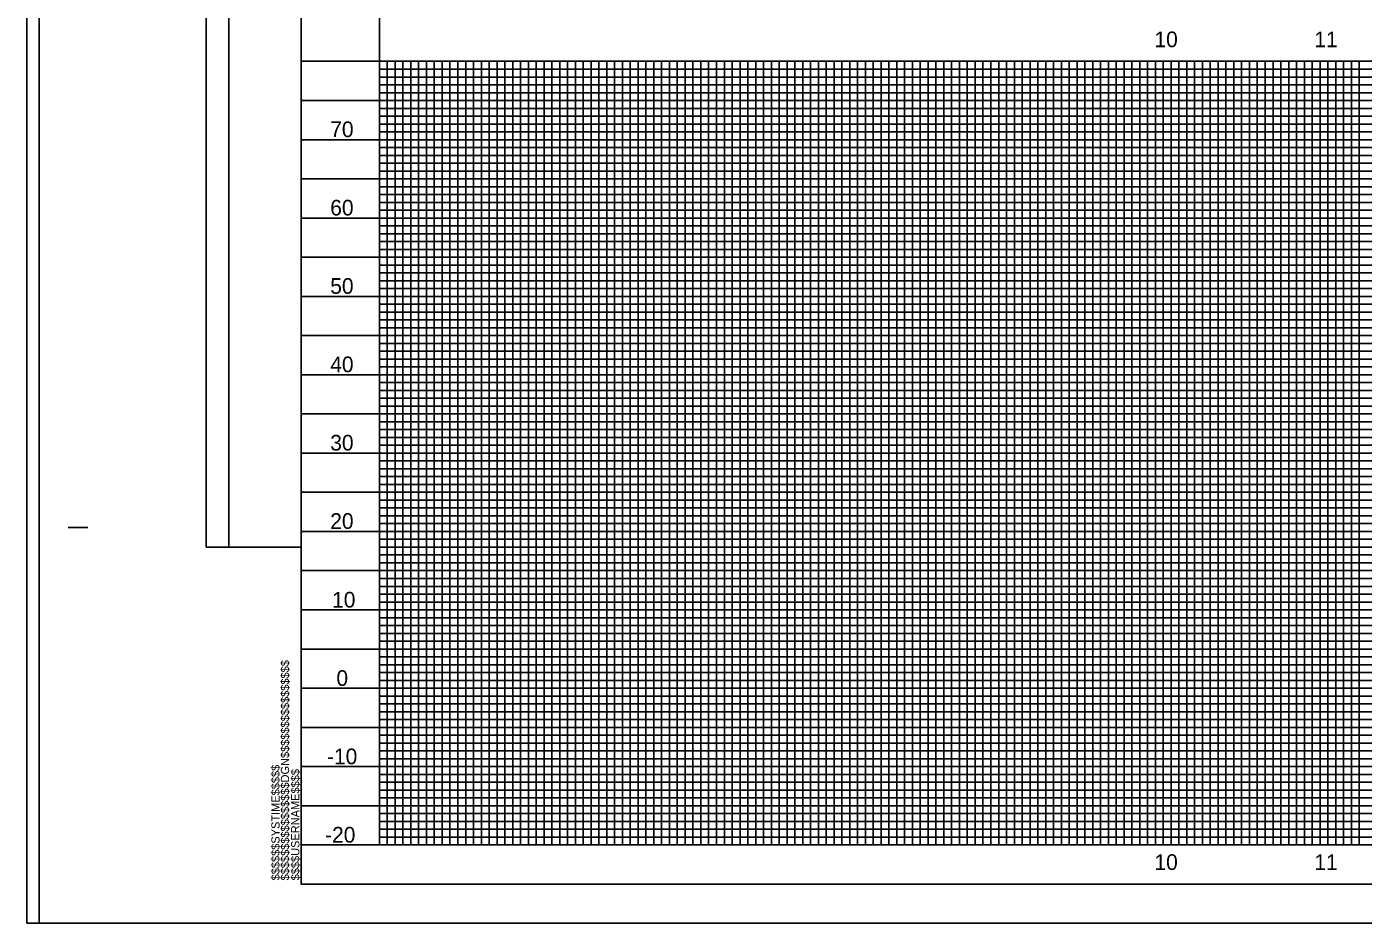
# Model space of a CAD drawing. Extents: x 1637092 to 1638792, y 884647 to 885778.
# Drawn here: x 1637092 to 1637944, y 884647 to 885219 of the extents above; entities that cross this region are included whole.
import ezdxf

# ---------------------------------------------------------------- set-up
doc = ezdxf.new("R2010")
doc.units = 0
for name, color, linetype in [('Exist Vertical Profile Horizontal Axis Label Major', 7, 'Continuous'), ('Exist Vertical Profile Vertical Axis Label', 7, 'Continuous'), ('Scratch_Level_3', 7, 'Continuous'), ('Sheet Block Revision CELL', 7, 'Continuous'), ('Sheet Block System Information CELL', 7, 'Continuous'), ('Sheet Cutting Line CELL', 7, 'Continuous'), ('Sheet DOT Grid CELL', 7, 'Continuous'), ('Sheet Layout Profile Border Port 2', 7, 'Continuous'), ('Sheet Plan And Profile CELL', 7, 'Continuous'), ('Sheet Profile CELL', 7, 'Continuous'), ('Sheet Profile Grid Major CELL', 7, 'Continuous'), ('Sheet Profile Grid Middle CELL', 7, 'Continuous'), ('Sheet Profile Grid Minor CELL', 7, 'Continuous'), ('Stewart Plot Border Xerox6279 and LJ5000', 7, 'Continuous')]:
    doc.layers.add(name, color=color, linetype=linetype)

msp = doc.modelspace()

# ---------------------------------------------------------------- linework, layer by layer
at = {"layer": 'Scratch_Level_3'}
msp.add_lwpolyline([(1637316.66, 885722.14), (1637316.66, 884697.14), (1638716.66, 884697.14), (1638716.66, 885777.71)], close=True, dxfattribs=at)
at = {"layer": 'Sheet Block Revision CELL'}
msp.add_line((1637220.66, 884887.14), (1637220.66, 885677.79), dxfattribs=at)
msp.add_lwpolyline([(1637206.11, 884887.14), (1637206.11, 885677.79), (1637266.66, 885677.79), (1637266.66, 884887.14)], close=True, dxfattribs=at)
at = {"layer": 'Sheet Block System Information CELL'}
msp.add_line((1637266.66, 884672.14), (1637266.66, 884672.14), dxfattribs=at)
at = {"layer": 'Sheet Cutting Line CELL'}
for p, q in [((1637099.66, 885747.14), (1637099.66, 884647.14)), ((1637099.66, 884647.14), (1638783.66, 884647.14))]:
    msp.add_line(p, q, dxfattribs=at)
at = {"layer": 'Sheet DOT Grid CELL'}
for p, q in [((1637266.66, 885197.14), (1638766.54, 885197.14)), ((1637316.66, 885197.14), (1637316.66, 884697.14)), ((1637366.66, 885197.14), (1637366.66, 884697.14)), ((1637416.66, 885197.14), (1637416.66, 884697.14)), ((1637466.66, 885197.14), (1637466.66, 884697.14)), ((1637516.66, 885197.14), (1637516.66, 884697.14)), ((1637566.66, 885197.14), (1637566.66, 884697.14)), ((1637616.66, 885197.14), (1637616.66, 884697.14)), ((1637666.66, 885197.14), (1637666.66, 884697.14)), ((1637716.66, 885197.14), (1637716.66, 884697.14)), ((1637766.66, 885197.14), (1637766.66, 884697.14)), ((1637816.66, 885197.14), (1637816.66, 884697.14)), ((1637866.66, 885197.14), (1637866.66, 884697.14)), ((1637916.66, 885197.14), (1637916.66, 884697.14)), ((1637266.66, 885147.14), (1638766.54, 885147.14)), ((1637266.66, 885097.14), (1638766.54, 885097.14)), ((1637266.66, 885047.14), (1638766.54, 885047.14)), ((1637266.66, 884997.14), (1638766.54, 884997.14)), ((1637266.66, 884947.14), (1638766.54, 884947.14)), ((1637266.66, 884897.14), (1638766.54, 884897.14)), ((1637266.66, 884847.14), (1638766.54, 884847.14)), ((1637266.66, 884797.14), (1638766.54, 884797.14)), ((1637266.66, 884747.14), (1638766.54, 884747.14))]:
    msp.add_line(p, q, dxfattribs=at)
at = {"layer": 'Sheet Layout Profile Border Port 2'}
msp.add_lwpolyline([(1637316.66, 885197.14), (1638716.66, 885197.14), (1638716.66, 884697.14), (1637316.66, 884697.14)], close=True, dxfattribs=at)
at = {"layer": 'Sheet Plan And Profile CELL'}
for p, q in [((1637118.16, 884899.64), (1637130.66, 884899.64)), ((1637266.66, 884672.14), (1637266.66, 884672.14)), ((1637266.66, 884672.14), (1637266.66, 884672.14)), ((1637266.66, 884672.14), (1637266.66, 884672.14)), ((1637266.66, 884672.14), (1637266.66, 884672.14)), ((1637266.66, 884672.14), (1637266.66, 884672.14))]:
    msp.add_line(p, q, dxfattribs=at)
msp.add_lwpolyline([(1638766.66, 885722.14), (1637266.66, 885722.14), (1637266.66, 884672.14), (1638766.66, 884672.14)], close=True, dxfattribs=at)
at = {"layer": 'Sheet Profile CELL'}
for p, q in [((1637266.66, 885197.14), (1638766.66, 885197.14)), ((1637118.16, 884899.64), (1637130.66, 884899.64)), ((1638766.66, 884697.14), (1637266.66, 884697.14)), ((1638766.66, 884697.14), (1637266.66, 884697.14)), ((1637266.66, 884672.14), (1638766.66, 884672.14)), ((1637266.66, 884672.14), (1637266.66, 884672.14)), ((1637266.66, 884672.14), (1637266.66, 884672.14)), ((1637266.66, 884672.14), (1637266.66, 884672.14)), ((1637266.66, 884672.14), (1637266.66, 884672.14)), ((1637266.66, 884672.14), (1637266.66, 884672.14)), ((1637266.66, 884672.14), (1637266.66, 884672.14)), ((1637266.66, 884672.14), (1637266.66, 884672.14))]:
    msp.add_line(p, q, dxfattribs=at)
msp.add_lwpolyline([(1638766.66, 885722.14), (1637266.66, 885722.14), (1637266.66, 884672.14), (1638766.66, 884672.14)], close=True, dxfattribs=at)
msp.add_lwpolyline([(1637304.16, 884672.14), (1637304.16, 884672.14)], dxfattribs=at)
at = {"layer": 'Sheet Profile Grid Major CELL'}
msp.add_line((1637266.66, 884697.14), (1637266.66, 884697.14), dxfattribs=at)
for points in [[(1637316.66, 885197.14), (1637316.66, 884697.14), (1637366.66, 884697.14), (1637366.66, 885197.14), (1637416.66, 885197.14), (1637416.66, 884697.14), (1637466.66, 884697.14), (1637466.66, 885197.14), (1637516.66, 885197.14), (1637516.66, 884697.14), (1637566.66, 884697.14), (1637566.66, 885197.14), (1637616.66, 885197.14), (1637616.66, 884697.14), (1637666.66, 884697.14), (1637666.66, 885197.14), (1637716.66, 885197.14), (1637716.66, 884697.14), (1637766.66, 884697.14), (1637766.66, 885197.14), (1637816.66, 885197.14), (1637816.66, 884697.14), (1637866.66, 884697.14), (1637866.66, 885197.14), (1637916.66, 885197.14), (1637916.66, 884697.14), (1637966.66, 884697.14)], [(1638766.66, 885147.14), (1637266.66, 885147.14)], [(1638766.66, 885097.14), (1637266.66, 885097.14), (1637266.66, 885047.14), (1638766.66, 885047.14)], [(1638766.66, 884997.14), (1637266.66, 884997.14), (1637266.66, 884947.14), (1638766.66, 884947.14)], [(1638766.66, 884897.14), (1637266.66, 884897.14), (1637266.66, 884847.14), (1638766.66, 884847.14)], [(1638766.66, 884797.14), (1637266.66, 884797.14), (1637266.66, 884797.14), (1637266.66, 884747.14), (1638766.66, 884747.14)], [(1638766.66, 884697.14), (1637266.66, 884697.14)]]:
    msp.add_lwpolyline(points, dxfattribs=at)
at = {"layer": 'Sheet Profile Grid Middle CELL'}
for points in [[(1637291.66, 885197.14), (1637341.66, 885197.14), (1637341.66, 884697.14), (1637391.66, 884697.14), (1637391.66, 885197.14), (1637441.66, 885197.14), (1637441.66, 884697.14), (1637491.66, 884697.14), (1637491.66, 885197.14), (1637541.66, 885197.14), (1637541.66, 884697.14), (1637591.66, 884697.14), (1637591.66, 885197.14), (1637641.66, 885197.14), (1637641.66, 884697.14), (1637691.66, 884697.14), (1637691.66, 885197.14), (1637741.66, 885197.14), (1637741.66, 884697.14), (1637791.66, 884697.14), (1637791.66, 885197.14), (1637841.66, 885197.14), (1637841.66, 884697.14), (1637891.66, 884697.14), (1637891.66, 884697.14), (1637891.66, 885197.14), (1637941.66, 885197.14), (1637941.66, 884697.14), (1637991.66, 884697.14)], [(1637266.66, 885172.14), (1638766.66, 885172.14)], [(1638766.66, 885122.14), (1637266.66, 885122.14), (1637266.66, 885072.14), (1638766.66, 885072.14)], [(1638766.66, 885022.14), (1637266.66, 885022.14), (1637266.66, 884972.14), (1638766.66, 884972.14)], [(1638766.66, 884922.14), (1637266.66, 884922.14), (1637266.66, 884872.14), (1638766.66, 884872.14)], [(1638766.66, 884822.14), (1637266.66, 884822.14), (1637266.66, 884772.14), (1638766.66, 884772.14)], [(1638766.66, 884722.14), (1637266.66, 884722.14)]]:
    msp.add_lwpolyline(points, dxfattribs=at)
at = {"layer": 'Sheet Profile Grid Minor CELL'}
for p, q in [((1637316.66, 885192.14), (1638716.66, 885192.14)), ((1638716.66, 885187.14), (1637316.66, 885187.14)), ((1637316.66, 885182.14), (1638716.66, 885182.14)), ((1638716.66, 885177.14), (1637316.66, 885177.14)), ((1637316.66, 885167.14), (1638716.66, 885167.14)), ((1638716.66, 885162.14), (1637316.66, 885162.14)), ((1637316.66, 885157.14), (1638716.66, 885157.14)), ((1638716.66, 885152.14), (1637316.66, 885152.14)), ((1637316.66, 885142.14), (1638716.66, 885142.14)), ((1638716.66, 885137.14), (1637316.66, 885137.14)), ((1637316.66, 885132.14), (1638716.66, 885132.14)), ((1638716.66, 885127.14), (1637316.66, 885127.14)), ((1637316.66, 885117.14), (1638716.66, 885117.14)), ((1638716.66, 885112.14), (1637316.66, 885112.14)), ((1637316.66, 885107.14), (1638716.66, 885107.14)), ((1638716.66, 885102.14), (1637316.66, 885102.14)), ((1637316.66, 885092.14), (1638716.66, 885092.14)), ((1638716.66, 885087.14), (1637316.66, 885087.14)), ((1637316.66, 885082.14), (1638716.66, 885082.14)), ((1638716.66, 885077.14), (1637316.66, 885077.14)), ((1637316.66, 885067.14), (1638716.66, 885067.14)), ((1638716.66, 885062.14), (1637316.66, 885062.14)), ((1637316.66, 885057.14), (1638716.66, 885057.14)), ((1638716.66, 885052.14), (1637316.66, 885052.14)), ((1637316.66, 885042.14), (1638716.66, 885042.14)), ((1638716.66, 885037.14), (1637316.66, 885037.14)), ((1637316.66, 885032.14), (1638716.66, 885032.14)), ((1638716.66, 885027.14), (1637316.66, 885027.14)), ((1637316.66, 885017.14), (1638716.66, 885017.14)), ((1638716.66, 885012.14), (1637316.66, 885012.14)), ((1637316.66, 885007.14), (1638716.66, 885007.14)), ((1638716.66, 885002.14), (1637316.66, 885002.29)), ((1637316.66, 884992.14), (1638716.66, 884992.14)), ((1638716.66, 884987.14), (1637316.66, 884987.14)), ((1637316.66, 884982.14), (1638716.66, 884982.14)), ((1638716.66, 884977.14), (1637316.66, 884977.14)), ((1637316.66, 884967.14), (1638716.66, 884967.14)), ((1638716.66, 884962.14), (1637316.66, 884962.14)), ((1637316.66, 884957.14), (1638716.66, 884957.14)), ((1638716.66, 884952.14), (1637316.66, 884952.14)), ((1637316.66, 884942.14), (1638716.66, 884942.14)), ((1638716.66, 884937.14), (1637316.66, 884937.14)), ((1637316.66, 884932.14), (1638716.66, 884932.14)), ((1638716.66, 884927.14), (1637316.66, 884927.14)), ((1637316.66, 884917.14), (1638716.66, 884917.14)), ((1638716.66, 884912.14), (1637316.66, 884912.14)), ((1637316.66, 884907.14), (1638716.66, 884907.14)), ((1638716.66, 884902.14), (1637316.66, 884902.14)), ((1637316.66, 884892.14), (1638716.66, 884892.14)), ((1638716.66, 884887.14), (1637316.66, 884887.14)), ((1637316.66, 884882.14), (1638716.66, 884882.14)), ((1638716.66, 884877.14), (1637316.66, 884877.14)), ((1637316.66, 884867.14), (1638716.66, 884867.14)), ((1638716.66, 884862.14), (1637316.66, 884862.14)), ((1637316.66, 884857.14), (1638716.66, 884857.14)), ((1638716.66, 884852.14), (1637316.66, 884852.14)), ((1637316.66, 884842.14), (1638716.66, 884842.14)), ((1638716.66, 884837.14), (1637316.66, 884837.14)), ((1637316.66, 884832.14), (1638716.66, 884832.14)), ((1638716.66, 884827.14), (1637316.66, 884827.14)), ((1637316.66, 884817.14), (1638716.66, 884817.14)), ((1638716.66, 884812.14), (1637316.66, 884812.14)), ((1637316.66, 884807.14), (1638716.66, 884807.14)), ((1638716.66, 884802.14), (1637316.66, 884802.14)), ((1637316.66, 884792.14), (1638716.66, 884792.14)), ((1638716.66, 884787.14), (1637316.66, 884787.14)), ((1637316.66, 884782.14), (1638716.66, 884782.14)), ((1638716.66, 884777.14), (1637316.66, 884777.14)), ((1637316.66, 884767.14), (1638716.66, 884767.14)), ((1638716.66, 884762.14), (1637316.66, 884762.14)), ((1637316.66, 884757.14), (1638716.66, 884757.14)), ((1638716.66, 884752.14), (1637316.66, 884752.14)), ((1637316.66, 884742.14), (1638716.66, 884742.14)), ((1638716.66, 884737.14), (1637316.66, 884737.14)), ((1637316.66, 884732.14), (1638716.66, 884732.14)), ((1638716.66, 884727.14), (1637316.66, 884727.14)), ((1637316.66, 884717.14), (1638716.66, 884717.14)), ((1638716.66, 884712.14), (1637316.66, 884712.14)), ((1637316.66, 884707.14), (1638716.66, 884707.14)), ((1637316.66, 884702.14), (1638716.66, 884702.14))]:
    msp.add_line(p, q, dxfattribs=at)
for points in [[(1637316.66, 885197.14), (1637321.66, 885197.14), (1637321.66, 884697.14), (1637326.66, 884697.14), (1637326.66, 885197.14), (1637331.66, 885197.14), (1637331.66, 884697.14), (1637336.66, 884697.14), (1637336.66, 885197.14), (1637346.66, 885197.14), (1637346.66, 884697.14), (1637351.66, 884697.14), (1637351.66, 885197.14), (1637356.66, 885197.14), (1637356.66, 884697.14), (1637361.66, 884697.14), (1637371.66, 884697.14), (1637376.66, 884697.14), (1637376.66, 885197.14), (1637381.66, 885197.14), (1637381.66, 884697.14), (1637386.66, 884697.14), (1637386.66, 885197.14), (1637396.66, 885197.14), (1637396.66, 884697.14), (1637401.66, 884697.14), (1637401.66, 885197.14), (1637406.66, 885197.14), (1637406.66, 884697.14), (1637411.66, 884697.14), (1637411.66, 885197.14), (1637421.66, 885197.14), (1637421.66, 884697.14), (1637426.66, 884697.14), (1637426.66, 885197.14), (1637431.66, 885197.14), (1637431.66, 884697.14), (1637436.66, 884697.14), (1637436.66, 885197.14), (1637446.66, 885197.14), (1637446.66, 884697.14), (1637451.66, 884697.14), (1637451.66, 885197.14), (1637456.66, 885197.14), (1637456.66, 884697.14), (1637461.66, 884697.14), (1637461.66, 885197.14), (1637471.66, 885197.14), (1637471.66, 884697.14), (1637476.66, 884697.14), (1637476.66, 885197.14), (1637481.66, 885197.14), (1637481.66, 884697.14), (1637486.66, 884697.14), (1637486.66, 885197.14), (1637496.66, 885197.14), (1637496.66, 884697.14), (1637501.66, 884697.14), (1637501.66, 885197.14), (1637506.66, 885197.14), (1637506.66, 884697.14), (1637511.66, 884697.14), (1637511.66, 885197.14), (1637521.66, 885197.14), (1637521.66, 884697.14), (1637526.66, 884697.14), (1637526.66, 885197.14), (1637531.66, 885197.14), (1637531.66, 884697.14)], [(1637361.66, 884697.14), (1637361.66, 885197.14), (1637371.66, 885197.14), (1637371.66, 884697.14)], [(1637531.66, 884697.14), (1637536.66, 884697.14), (1637536.66, 885197.14), (1637546.66, 885197.14), (1637546.66, 884697.14), (1637551.66, 884697.14), (1637551.66, 885197.14), (1637556.66, 885197.14), (1637556.66, 884697.14), (1637561.66, 884697.14), (1637561.66, 885197.14), (1637571.66, 885197.14), (1637571.66, 884697.14), (1637576.66, 884697.14), (1637576.66, 885197.14), (1637581.66, 885197.14), (1637581.66, 884697.14), (1637586.66, 884697.14), (1637586.66, 885197.14), (1637596.66, 885197.14), (1637596.66, 884697.14), (1637601.66, 884697.14), (1637601.66, 885197.14), (1637606.66, 885197.14), (1637606.66, 884697.14), (1637611.66, 884697.14), (1637611.66, 885197.14), (1637621.66, 885197.14), (1637621.66, 884697.14), (1637626.66, 884697.14), (1637626.66, 885197.14), (1637631.66, 885197.14), (1637631.66, 884697.14), (1637636.66, 884697.14), (1637636.66, 885197.14), (1637646.66, 885197.14), (1637646.66, 884697.14), (1637651.66, 884697.14), (1637651.66, 885197.14), (1637656.66, 885197.14), (1637656.66, 884697.14), (1637661.66, 884697.14), (1637661.66, 885197.14), (1637671.66, 885197.14), (1637671.66, 884697.14), (1637676.66, 884697.14), (1637676.66, 885197.14), (1637681.66, 885197.14), (1637681.66, 884697.14), (1637686.66, 884697.14), (1637686.66, 885197.14), (1637696.66, 885197.14), (1637696.66, 884697.14), (1637701.66, 884697.14), (1637701.66, 885197.14), (1637706.66, 885197.14), (1637706.66, 884697.14), (1637711.66, 884697.14), (1637711.66, 885197.14), (1637721.66, 885197.14), (1637721.66, 884697.14), (1637726.66, 884697.14), (1637726.66, 885197.14), (1637731.66, 885197.14), (1637731.66, 884697.14), (1637736.66, 884697.14), (1637736.66, 885197.14), (1637746.66, 885197.14), (1637746.66, 884697.14), (1637751.66, 884697.14), (1637751.66, 885197.14), (1637756.66, 885197.14), (1637756.66, 884697.14), (1637761.66, 884697.14), (1637761.66, 885197.14), (1637771.66, 885197.14), (1637771.66, 884697.14), (1637776.66, 884697.14), (1637776.66, 885197.14), (1637781.66, 885197.14), (1637781.66, 884697.14), (1637786.66, 884697.14), (1637786.66, 885197.14), (1637796.66, 885197.14), (1637796.66, 884697.14), (1637801.66, 884697.14), (1637801.66, 885197.14), (1637806.66, 885197.14), (1637806.66, 884697.14), (1637811.66, 884697.14), (1637811.66, 885197.14), (1637821.66, 885197.14), (1637821.66, 884697.14), (1637826.66, 884697.14), (1637826.66, 885197.14), (1637831.66, 885197.14), (1637831.66, 884697.14), (1637836.66, 884697.14), (1637836.66, 885197.14), (1637846.66, 885197.14)], [(1637846.66, 885197.14), (1637846.66, 884697.14), (1637851.66, 884697.14), (1637851.66, 885197.14), (1637856.66, 885197.14), (1637856.66, 884697.14), (1637861.66, 884697.14), (1637861.66, 885197.14), (1637871.66, 885197.14), (1637871.66, 884697.14), (1637876.66, 884697.14), (1637876.66, 885197.14), (1637881.66, 885197.14), (1637881.66, 884697.14), (1637886.66, 884697.14), (1637886.66, 885197.14), (1637896.66, 885197.14), (1637896.66, 884697.14), (1637901.66, 884697.14), (1637901.66, 885197.14), (1637906.66, 885197.14), (1637906.66, 884697.14), (1637911.66, 884697.14), (1637911.66, 885197.14), (1637921.66, 885197.14), (1637921.66, 884697.14), (1637926.66, 884697.14), (1637926.66, 885197.14), (1637931.66, 885197.14), (1637931.66, 884697.14), (1637936.66, 884697.14), (1637936.66, 885197.14), (1637946.66, 885197.14)]]:
    msp.add_lwpolyline(points, dxfattribs=at)
at = {"layer": 'Stewart Plot Border Xerox6279 and LJ5000'}
msp.add_lwpolyline([(1637091.66, 884647.14), (1638791.66, 884647.14), (1638791.66, 885747.14), (1637091.66, 885747.14)], close=True, dxfattribs=at)

# ---------------------------------------------------------------- texts
at = {"layer": 'Exist Vertical Profile Horizontal Axis Label Major'}
for s, p in [('10', (1637811.04, 885206.16)), ('11', (1637913.02, 885206.16)), ('10', (1637811.04, 884681.16)), ('11', (1637913.02, 884681.16))]:
    msp.add_text(s, height=10, dxfattribs=at).set_placement(p)
at = {"layer": 'Exist Vertical Profile Vertical Axis Label'}
for s, p in [('70', (1637285.27, 885148.79)), ('60', (1637285.27, 885098.79)), ('50', (1637285.27, 885048.79)), ('40', (1637285.27, 884998.79)), ('30', (1637285.27, 884948.79)), ('20', (1637285.27, 884898.79)), ('10', (1637286.46, 884848.61)), ('0', (1637289.22, 884798.61)), ('-10', (1637283.19, 884748.61)), ('-20', (1637281.99, 884698.61))]:
    msp.add_text(s, height=10, dxfattribs=at).set_placement(p)
at = {"layer": 'Sheet Block System Information CELL'}
for s, p in [('$$$$$$$$$$$$$$$$DGN$$$$$$$$$$$$$$$$', (1637259.01, 884674.5)), ('$$$$$$SYSTIME$$$$$', (1637252.96, 884674.5)), ('$$$$USERNAME$$$$', (1637265.58, 884674.52))]:
    msp.add_text(s, height=5.25, rotation=90, dxfattribs=at).set_placement(p)
at = {"layer": 'Sheet Profile CELL'}
for s, p in [('$$$$$$$$$$$$$$$$DGN$$$$$$$$$$$$$$$$', (1637259.02, 884674.52)), ('$$$$$$SYSTIME$$$$$', (1637252.97, 884674.52)), ('$$$$USERNAME$$$$', (1637265.59, 884674.53))]:
    msp.add_text(s, height=5.25, rotation=90, dxfattribs=at).set_placement(p)

doc.saveas('drawing.dxf')
